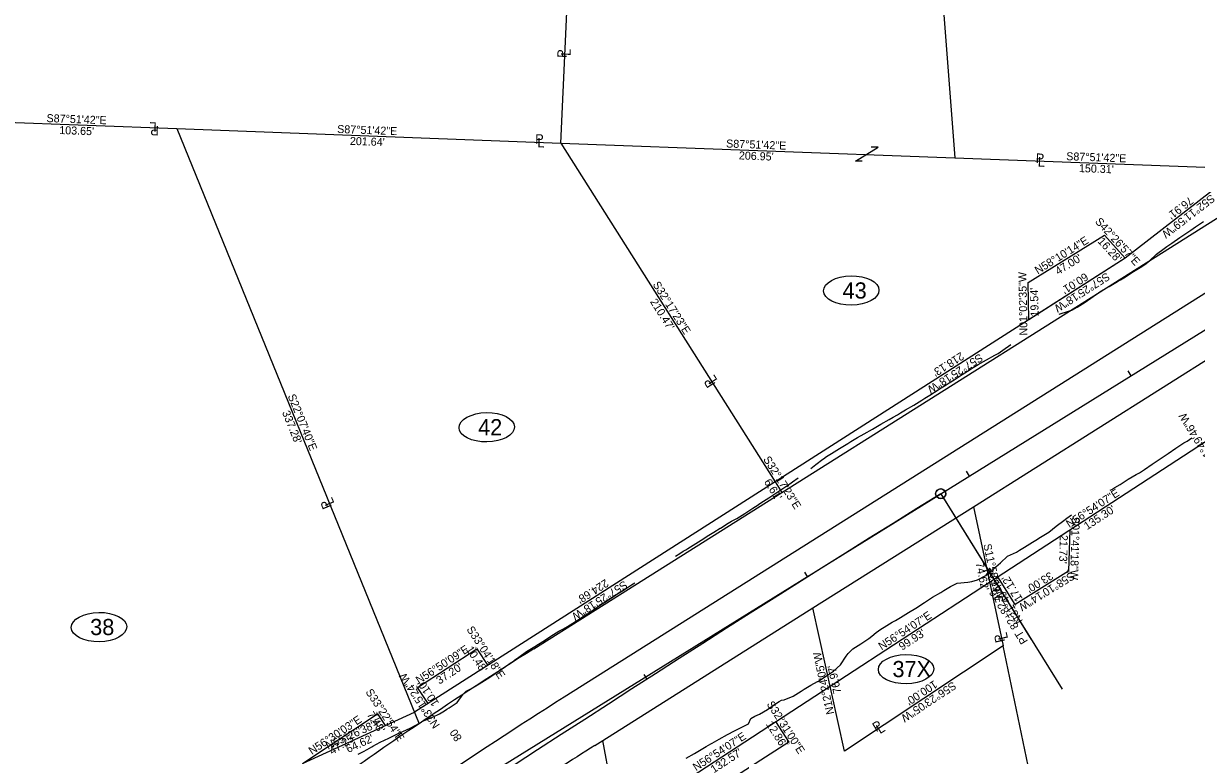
# Model space of a CAD drawing. Extents: x 1145508 to 2262867, y -3126236 to 2021677.
# Drawn here: x 1150426 to 1151042, y 2019881 to 2020265 of the extents above; entities that cross this region are included whole.
import ezdxf

# ---------------------------------------------------------------- set-up
doc = ezdxf.new("R2010")
doc.units = 0
for name, color, linetype in [('Default', 7, 'Continuous'), ('DSN_RDWY_Alignment', 7, 'Continuous'), ('DSN_RDWY_Alignment Annotation', 7, 'Continuous'), ('DSN_RDWY_Const Limits', 7, 'Continuous'), ('DSN_ROW_Annotation', 7, 'Continuous'), ('DSN_ROW_Esmnt', 7, 'Continuous'), ('DSN_ROW_Line', 7, 'Continuous'), ('DSN_ROW_Line-Annotation', 7, 'Continuous'), ('DSN_ROW_Prop-Line', 7, 'Continuous'), ('DSN_ROW_Prop-Line-Annotation', 7, 'Continuous'), ('E_Const Align', 7, 'Continuous'), ('EX_QSECTION', 7, 'Continuous'), ('EX_ROW', 7, 'Continuous'), ('EX_ROW_ANNOT', 7, 'Continuous')]:
    doc.layers.add(name, color=color, linetype=linetype)

msp = doc.modelspace()

# ---------------------------------------------------------------- linework, layer by layer
at = {"layer": 'Default'}
msp.add_line((1151129.4, 2020175.6), (1150710.33, 2019911.3), dxfattribs=at)
msp.add_arc((1151932.9, 2017972.79), 2291.83, 122.23857, 126.5246, dxfattribs=at)
at = {"layer": 'DSN_RDWY_Alignment'}
msp.add_line((1150506.7, 2019769.08), (1150907.91, 2020018.13), dxfattribs=at)
msp.add_lwpolyline([(1150907.91, 2020018.13), (1150971.61, 2019915.52)], dxfattribs=at)
msp.add_circle((1150907.91, 2020018.13), 2.5, dxfattribs=at)
at = {"layer": 'DSN_RDWY_Alignment Annotation'}
for p, q in [((1151006.19, 2020082.66), (1151007.77, 2020080.11)), ((1150921.23, 2020029.92), (1150922.81, 2020027.37)), ((1150907.91, 2020018.13), (1150907.91, 2020018.13)), ((1150909.32, 2020015.86), (1150955.38, 2019941.66)), ((1150836.41, 2019976.92), (1150838.01, 2019974.38)), ((1150955.38, 2019941.66), (1150955.38, 2019941.66)), ((1150752.04, 2019923.19), (1150753.66, 2019920.67))]:
    msp.add_line(p, q, dxfattribs=at)
msp.add_circle((1150907.91, 2020018.13), 2.67, dxfattribs=at)
at = {"layer": 'DSN_RDWY_Const Limits'}
for points in [[(1150970.06, 2020112.42), (1150974.97, 2020113.99), (1150976.8, 2020114.56), (1150979.6, 2020116.02), (1150983.77, 2020118.78), (1150987.9, 2020121.61), (1150989.46, 2020122.68), (1150992.03, 2020124.41), (1150992.04, 2020124.42), (1150996.35, 2020126.96), (1151000.66, 2020129.49), (1151002.29, 2020130.45), (1151004.93, 2020132.09), (1151009.13, 2020134.81), (1151013.39, 2020137.42), (1151014.97, 2020138.4), (1151017.41, 2020140.43), (1151021.16, 2020143.87), (1151025.14, 2020146.95), (1151026.68, 2020147.98), (1151029.27, 2020149.77), (1151033.38, 2020152.63), (1151037.53, 2020155.43), (1151039.12, 2020156.5), (1151041.66, 2020158.25), (1151045.83, 2020161)], [(1150839.66, 2020031.42), (1150842.32, 2020033.41), (1150845.98, 2020036.2), (1150846.33, 2020036.47), (1150847.97, 2020037.6), (1150850.55, 2020039.2), (1150854.82, 2020041.84), (1150859.09, 2020044.48), (1150860.76, 2020045.51), (1150863.36, 2020047.12), (1150864.23, 2020047.66), (1150867.71, 2020049.63), (1150872.11, 2020052.07), (1150873.82, 2020053.02), (1150876.47, 2020054.56), (1150880.82, 2020057.07), (1150882.97, 2020058.31), (1150885.16, 2020059.58), (1150886.78, 2020060.52), (1150889.49, 2020062.09), (1150893.79, 2020064.64), (1150898.03, 2020067.29), (1150899.62, 2020068.29), (1150902.27, 2020069.95), (1150906.51, 2020072.6), (1150908.2, 2020073.67), (1150910.74, 2020075.27), (1150912.32, 2020076.27), (1150914.96, 2020077.94), (1150919.17, 2020080.64), (1150923.37, 2020083.35), (1150924.94, 2020084.37), (1150927.6, 2020086.02), (1150931.98, 2020088.45), (1150936.36, 2020090.88), (1150938, 2020091.83), (1150940.57, 2020093.58), (1150944.7, 2020096.4)], [(1150996.87, 2020019.9), (1150997.74, 2020020.42), (1150999.36, 2020021.37), (1151002.05, 2020022.97), (1151006.23, 2020025.72), (1151010.53, 2020028.28), (1151012.2, 2020029.12), (1151014.84, 2020030.81), (1151018.96, 2020033.64), (1151023.09, 2020036.47), (1151024.63, 2020037.51), (1151027.23, 2020039.28), (1151031.39, 2020042.06), (1151035.6, 2020044.76), (1151037.19, 2020045.78), (1151039.8, 2020047.46)], [(1150768.67, 2019985.27), (1150770.9, 2019986.67), (1150772.82, 2019987.87), (1150774.09, 2019988.67), (1150775.16, 2019989.33), (1150779.39, 2019992.04), (1150783.65, 2019994.69), (1150785.38, 2019995.77), (1150787.91, 2019997.35), (1150788.76, 2019997.88), (1150792.17, 2020000), (1150792.34, 2020000.11), (1150796.43, 2020002.65), (1150798.14, 2020003.71), (1150800.87, 2020005.03), (1150805.09, 2020007.75), (1150809.28, 2020010.51), (1150810.67, 2020011.43), (1150811.04, 2020011.67), (1150813.49, 2020013.25), (1150817.69, 2020015.99), (1150821.88, 2020018.77), (1150823.55, 2020019.87), (1150826.07, 2020021.54), (1150828.64, 2020023.32), (1150830.19, 2020024.41), (1150833.03, 2020026.44)], [(1150774.37, 2019879.25), (1150778.67, 2019881.77), (1150782.99, 2019884.26), (1150784.89, 2019885.36), (1150787.31, 2019886.75), (1150788.04, 2019887.17), (1150791.63, 2019889.24), (1150795.95, 2019891.73), (1150797.73, 2019892.64), (1150797.88, 2019892.72), (1150800.41, 2019893.98), (1150804.9, 2019896.22), (1150806.95, 2019897.25), (1150808.32, 2019900.1), (1150810.28, 2019901.26), (1150812.77, 2019902.38), (1150817.08, 2019904.89), (1150821.14, 2019907.79), (1150823.06, 2019908.95), (1150824.34, 2019909.72), (1150825.75, 2019909.82), (1150830.39, 2019911.8), (1150834.62, 2019914.42), (1150836.3, 2019915.55), (1150838.82, 2019917.1), (1150839.73, 2019917.53), (1150843.22, 2019919.45), (1150843.39, 2019919.56), (1150847.4, 2019922.16), (1150849.07, 2019923.24), (1150851.57, 2019924.88), (1150855.28, 2019928.32), (1150858.35, 2019932.8), (1150859.41, 2019934.21), (1150859.7, 2019934.58), (1150861.8, 2019936.65), (1150866.07, 2019939.22), (1150870.19, 2019942.03), (1150871.74, 2019943.3), (1150874.07, 2019945.21), (1150876.57, 2019947.06), (1150878.15, 2019948.08), (1150882.44, 2019950.62), (1150884.12, 2019951.61), (1150886.73, 2019953.15), (1150891.02, 2019955.68), (1150894.91, 2019958.03), (1150895.27, 2019958.28), (1150896.89, 2019959.41), (1150899.41, 2019961.06), (1150903.6, 2019963.74), (1150907.92, 2019966.24), (1150909.59, 2019967.22), (1150912.18, 2019968.81), (1150913.04, 2019969.34), (1150916.6, 2019971.14), (1150922.1, 2019971.74), (1150924.24, 2019971.97), (1150927.23, 2019972.91), (1150931.63, 2019975.26), (1150933.58, 2019976.78), (1150935.5, 2019978.48), (1150936.92, 2019979.74), (1150939.29, 2019981.86), (1150943.03, 2019985.31), (1150947.65, 2019987.35), (1150949.2, 2019988.4), (1150951.86, 2019990.06), (1150956.11, 2019992.7), (1150957.81, 2019993.74), (1150960.36, 2019995.32), (1150961.96, 2019996.29), (1150964.6, 2019997.97), (1150968.57, 2020001.05), (1150972.55, 2020004.12), (1150974.07, 2020005.23), (1150976.58, 2020007.12)], [(1150602.19, 2019881.4), (1150604.89, 2019882.79), (1150606.82, 2019883.8), (1150609.34, 2019885.16), (1150609.94, 2019885.49), (1150613.69, 2019887.68), (1150618.29, 2019889.82), (1150620.28, 2019890.76), (1150622.87, 2019892), (1150627.45, 2019894.17), (1150629.4, 2019895.1), (1150631.99, 2019896.41), (1150633.97, 2019897.44), (1150636.4, 2019898.83), (1150641.11, 2019900.8), (1150644.91, 2019902.5), (1150645.67, 2019903), (1150647.51, 2019904.2), (1150648.69, 2019904.96), (1150649.88, 2019905.74), (1150654.1, 2019908.45), (1150657.26, 2019912.79), (1150658.87, 2019914.43), (1150661.33, 2019915.74), (1150665.65, 2019918.31), (1150665.68, 2019918.33), (1150669.94, 2019920.92), (1150671.79, 2019922.13), (1150674.11, 2019923.72), (1150678.24, 2019926.57), (1150682.38, 2019929.42), (1150683.61, 2019930.26), (1150684.26, 2019930.71), (1150686.52, 2019932.26), (1150690.52, 2019935.32), (1150693.13, 2019936.83), (1150694.83, 2019937.9), (1150696.77, 2019939.13), (1150699.07, 2019940.59), (1150701.57, 2019942.16), (1150703.32, 2019943.27), (1150707.56, 2019945.94), (1150709.56, 2019947.03), (1150711.94, 2019948.41), (1150716.19, 2019951.09), (1150719.92, 2019953.44), (1150720.44, 2019953.76), (1150722.34, 2019954.96), (1150724.69, 2019956.44), (1150728.78, 2019959.35), (1150732.99, 2019962.1), (1150734.84, 2019963.3), (1150737.19, 2019964.84), (1150737.9, 2019965.3), (1150741.41, 2019967.56), (1150745.62, 2019970.3), (1150747.3, 2019971.39)]]:
    msp.add_lwpolyline(points, dxfattribs=at)
at = {"layer": 'DSN_ROW_Esmnt'}
for p, q in [((1150953.86, 2020129.04), (1150993.8, 2020153.83)), ((1150993.8, 2020153.83), (1151004.78, 2020141.81)), ((1151004.78, 2020141.81), (1150954.22, 2020109.51)), ((1150954.22, 2020109.51), (1150953.86, 2020129.04)), ((1150975.66, 2019999.12), (1150975.02, 2019977.39)), ((1150946.98, 2019959.99), (1150937.95, 2019974.54)), ((1150975.02, 2019977.39), (1150946.98, 2019959.99)), ((1150633.28, 2019916.41), (1150664.42, 2019936.76)), ((1150664.42, 2019936.76), (1150670.14, 2019927.98)), ((1150638.82, 2019907.97), (1150633.28, 2019916.41)), ((1150572.87, 2019876.53), (1150612.27, 2019902.61)), ((1150612.27, 2019902.61), (1150616.36, 2019896.4)), ((1150821.2, 2019898.43), (1150828.11, 2019887.59)), ((1150828.11, 2019887.59), (1150777.9, 2019855.4))]:
    msp.add_line(p, q, dxfattribs=at)
at = {"layer": 'DSN_ROW_Line'}
for p, q in [((1151065.55, 2020188.95), (1151004.78, 2020141.81)), ((1151004.78, 2020141.81), (1150820.98, 2020024.36)), ((1150933.54, 2019971.66), (1151046.89, 2020045.54)), ((1150820.98, 2020024.36), (1150631.65, 2019903.38)), ((1150849.82, 2019917.09), (1150933.54, 2019971.66)), ((1150738.77, 2019844.7), (1150849.82, 2019917.09)), ((1150572.87, 2019876.53), (1150631.65, 2019903.38))]:
    msp.add_line(p, q, dxfattribs=at)
at = {"layer": 'DSN_ROW_Line-Annotation'}
for centre in [(1150860.96, 2020124.81), (1150669.63, 2020053.01), (1150466.14, 2019948.09), (1150889.74, 2019926.01)]:
    msp.add_ellipse(centre, major_axis=(14.54, 0.23), ratio=0.529773, dxfattribs=at)
at = {"layer": 'DSN_ROW_Prop-Line'}
for p, q in [((1150879.93, 2020650.4), (1150915.35, 2020194.56)), ((1150708.55, 2020202.28), (1150716.19, 2020370.41)), ((1150507.05, 2020209.81), (1150634.09, 2019897.37)), ((1150708.55, 2020202.28), (1150820.98, 2020024.36)), ((1150820.98, 2020024.36), (1150824.51, 2020018.78)), ((1150925.13, 2020011.3), (1150940.61, 2019938.3)), ((1150857.33, 2019882.94), (1150840.8, 2019958.12)), ((1150940.61, 2019938.3), (1150857.33, 2019882.94)), ((1150986.32, 2019721.27), (1150940.61, 2019938.3)), ((1150769.39, 2019682.28), (1150730.49, 2019888.55))]:
    msp.add_line(p, q, dxfattribs=at)
at = {"layer": 'DSN_ROW_Prop-Line-Annotation'}
for p, q in [((1150863.16, 2020192.67), (1150875.02, 2020200.06)), ((1150875.02, 2020200.06), (1150871.47, 2020200.06)), ((1150866.71, 2020192.67), (1150863.16, 2020192.67))]:
    msp.add_line(p, q, dxfattribs=at)
at = {"layer": 'E_Const Align'}
msp.add_line((1150907.91, 2020018.13), (1151211.88, 2020206.81), dxfattribs=at)
msp.add_arc((1156951.39, 2010282.18), 11459.16, 121.829445, 126.548983, dxfattribs=at)
msp.add_arc((1156951.39, 2010282.18), 11459.16, 121.829445, 126.548983, dxfattribs=at)
at = {"layer": 'EX_QSECTION'}
for p, q in [((1150403.47, 2020213.68), (1150507.05, 2020209.81)), ((1150507.05, 2020209.81), (1150708.55, 2020202.28)), ((1150708.55, 2020202.28), (1150915.35, 2020194.56)), ((1150915.35, 2020194.56), (1151065.55, 2020188.95))]:
    msp.add_line(p, q, dxfattribs=at)
at = {"layer": 'EX_ROW'}
for p, q in [((1150824.51, 2020018.78), (1151092.73, 2020187.94)), ((1150925.13, 2020011.3), (1151145.4, 2020150.22)), ((1150694.33, 2019936.68), (1150824.51, 2020018.78)), ((1150840.8, 2019958.12), (1150925.13, 2020011.3)), ((1150730.49, 2019888.55), (1150840.8, 2019958.12)), ((1150726.33, 2019885.92), (1150730.49, 2019888.55))]:
    msp.add_line(p, q, dxfattribs=at)
for radius, start, end in [(2321.83, 122.23857, 124.0135), (2321.83, 124.0135, 126.5246), (2261.83, 122.23857, 122.79592)]:
    msp.add_arc((1151932.9, 2017972.79), radius, start, end, dxfattribs=at)

# ---------------------------------------------------------------- texts
at = {"layer": 'DSN_RDWY_Alignment Annotation'}
for s, rotation, p in [('82+82.46', 121.82944, (1150949.07, 2019948.4)), ('PT', 121.82944, (1150953.85, 2019940.71)), ('80', 123.24177, (1150656.84, 2019889.8))]:
    msp.add_text(s, height=4.2, rotation=rotation, dxfattribs=at).set_placement(p)
at = {"layer": 'DSN_ROW_Annotation'}
for s, rotation, p in [('S52°11\'59"W', 217.80015, (1151049.76, 2020175.57)), ("76.91'", 217.80015, (1151038.48, 2020174.41)), ('S42°26\'57"E', 312.4491, (1150988.64, 2020160.8)), ('N58°10\'14"E', 31.82944, (1150958.86, 2020133.2)), ("16.28'", 312.4491, (1150990.02, 2020150.39)), ("47.00'", 31.82944, (1150969.59, 2020132.8)), ('N01°02\'35"W', 91.04296, (1150953.47, 2020101.19)), ('S57°25\'18"W', 212.57822, (1150994.96, 2020134.47)), ('S32°17\'23"E', 302.28972, (1150756.57, 2020127.98)), ("60.01'", 212.57822, (1150983.62, 2020134.35)), ("19.54'", 91.04296, (1150959.29, 2020111.21)), ("210.47'", 302.28972, (1150755.18, 2020118.93)), ('S57°25\'18"W', 212.57822, (1150928.34, 2020091.9)), ("218.13'", 212.57822, (1150918.44, 2020092.7)), ('S22°07\'40"E', 292.12777, (1150565.09, 2020069.45)), ("337.28'", 292.12777, (1150562.13, 2020060.8)), ('N31°49\'46"W', 121.82945, (1151053.8, 2020032.69)), ('S32°17\'23"E', 302.28972, (1150814.55, 2020036.22)), ("6.61'", 302.28972, (1150814.99, 2020024.3)), ('N56°54\'07"E', 33.09797, (1150975.43, 2020000.04)), ("135.30'", 33.09797, (1150984.74, 2019998.94)), ('S01°41\'18"W', 268.31166, (1150976.77, 2020005.99)), ("21.73'", 268.31166, (1150970.48, 2019996.55)), ('S11°58\'19"E', 281.97195, (1150930.27, 2019991.39)), ("74.62'", 281.97195, (1150926.19, 2019981.72)), ('N31°49\'46"W', 121.82944, (1150951.23, 2019951.44)), ("17.12'", 121.82944, (1150951.1, 2019963.02)), ('S58°10\'14"W', 211.82944, (1150976.58, 2019977.3)), ("33.00'", 211.82944, (1150965.24, 2019977.32)), ('S57°25\'18"W', 212.57822, (1150741.77, 2019972.68)), ("224.68'", 212.57822, (1150731.87, 2019973.48)), ('N56°54\'07"E', 33.09797, (1150876.9, 2019935.81)), ('S33°04\'18"E', 303.07177, (1150658.88, 2019946.91)), ("99.93'", 33.09797, (1150887.64, 2019935.65)), ('N56°50\'09"E', 33.16427, (1150634.08, 2019918.01)), ("10.48'", 303.07177, (1150658.55, 2019936.42)), ('N12°24\'05"W', 102.40147, (1150852.07, 2019902.69)), ("37.20'", 33.16427, (1150644.81, 2019917.86)), ("76.97'", 102.40147, (1150855.8, 2019913.66)), ('N33°15\'24"W', 123.25677, (1150645.2, 2019896.59)), ("10.10'", 123.25677, (1150644.78, 2019908.17)), ('S56°23\'05"W', 213.61538, (1150914.27, 2019919.71)), ("100.00'", 213.61538, (1150904.36, 2019920.33)), ('S33°22\'54"E', 303.38177, (1150605.85, 2019914)), ('S32°31\'00"E', 302.51677, (1150816.4, 2019907.63)), ('N56°30\'03"E', 33.49927, (1150577.85, 2019880.9)), ('N65°26\'38"E', 24.55619, (1150586.37, 2019883.69)), ("7.43'", 303.38177, (1150606.51, 2019902.08)), ("12.86'", 302.51677, (1150815.97, 2019897.14)), ("47.25'", 33.49927, (1150588.59, 2019880.82)), ("64.62'", 24.55619, (1150596.96, 2019881.93)), ('N56°54\'07"E', 33.09799, (1150779.52, 2019872.33)), ("132.57'", 33.09799, (1150788.82, 2019871.24))]:
    msp.add_text(s, height=4.2, rotation=rotation, dxfattribs=at).set_placement(p)
at = {"layer": 'DSN_ROW_Esmnt'}
for p in [(1150974.02, 2019976.39), (1150945.98, 2019958.99), (1150663.42, 2019935.76), (1150632.28, 2019915.41), (1150611.27, 2019901.61), (1150827.11, 2019886.59)]:
    msp.add_text('b', height=2, dxfattribs=at).set_placement(p)
at = {"layer": 'DSN_ROW_Line-Annotation'}
for s, p in [('43', (1150856.42, 2020120.6)), ('42', (1150665.13, 2020048.81)), ('38', (1150461.5, 2019943.88)), ('37X', (1150882.6, 2019921.81))]:
    msp.add_text(s, height=8.5, dxfattribs=at).set_placement(p)
at = {"layer": 'DSN_ROW_Prop-Line-Annotation'}
for s, rotation, p in [('P', 87.55888, (1150711.62, 2020246.88)), ('L', 87.55888, (1150713.59, 2020247.97)), ('L', 178.58941, (1150496.47, 2020213.14)), ('P', 178.58941, (1150497.59, 2020211.2)), ('P', 359.08257, (1150695.02, 2020201.91)), ('L', 359.08257, (1150696.16, 2020199.97)), ('P', 357.69021, (1150957.71, 2020191.85)), ('L', 357.69021, (1150958.8, 2020189.89)), ('L', 122.39495, (1150790.89, 2020077.81)), ('P', 122.39495, (1150789.9, 2020075.8)), ('P', 112.54436, (1150588.45, 2020011.32)), ('L', 112.54436, (1150589.78, 2020013.13)), ('P', 102.83695, (1150941.68, 2019940.53)), ('L', 102.83695, (1150943.29, 2019942.09)), ('P', 32.04932, (1150874.04, 2019892.83)), ('L', 32.04932, (1150876.05, 2019891.83))]:
    msp.add_text(s, height=5, rotation=rotation, dxfattribs=at).set_placement(p)
at = {"layer": 'EX_ROW_ANNOT'}
for s, p in [('S87°51\'42"E', (1150438.54, 2020213.27)), ('S87°51\'42"E', (1150438.54, 2020213.27)), ("103.65'", (1150445.22, 2020207.01)), ("103.65'", (1150445.22, 2020207.01)), ('S87°51\'42"E', (1150591.08, 2020207.57)), ('S87°51\'42"E', (1150591.08, 2020207.57)), ("201.64'", (1150597.76, 2020201.32)), ("201.64'", (1150597.76, 2020201.32)), ('S87°51\'42"E', (1150795.23, 2020199.95)), ('S87°51\'42"E', (1150795.23, 2020199.95)), ("206.95'", (1150801.91, 2020193.69)), ("206.95'", (1150801.91, 2020193.69)), ('S87°51\'42"E', (1150973.73, 2020193.28)), ('S87°51\'42"E', (1150973.73, 2020193.28)), ("150.31'", (1150980.41, 2020187.03)), ("150.31'", (1150980.41, 2020187.03))]:
    msp.add_text(s, height=4.2, rotation=357.86155, dxfattribs=at).set_placement(p)

doc.saveas('drawing.dxf')
